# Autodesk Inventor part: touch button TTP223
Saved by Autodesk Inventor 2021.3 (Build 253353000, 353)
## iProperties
Created: 2023-07
Part Number: touch button TTP223
Material: Generic
Document SubType Name: Modeling
Designer: AdminForWorker
Density: 1 g/cm^3
Appearance: Default
Title: touch button TTP223 v1
Author: AdminForWorker
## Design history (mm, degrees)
feature "Body1"
body "Solid1"
